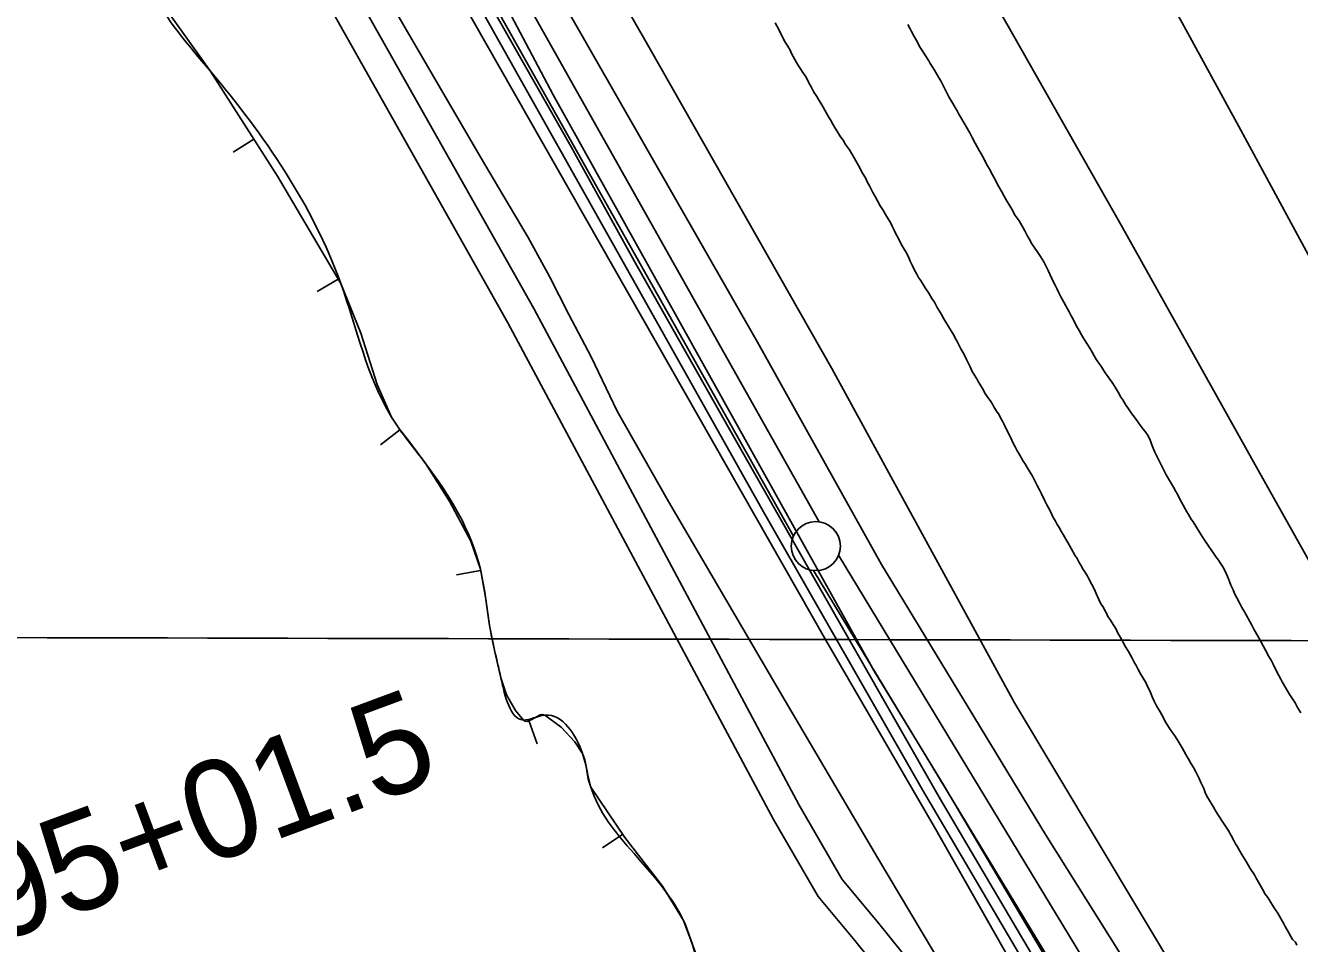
# Model space of a CAD drawing. Extents: x 3187622 to 3225504, y 800805 to 826213.
# Drawn here: x 3195483 to 3196782, y 818051 to 818987 of the extents above; entities that cross this region are included whole.
import ezdxf

# ---------------------------------------------------------------- set-up
doc = ezdxf.new("R2010")
doc.units = 0
for name, color, linetype in [('V-BORW-LINE', 7, 'Continuous'), ('V-GRID-MAJR', 7, 'Continuous'), ('V-LEVE-TOET', 7, 'Continuous'), ('V-RAIL-TRAK', 7, 'Continuous'), ('V-ROAD-CNTR', 7, 'Continuous'), ('V-SURV-IDEN', 7, 'Continuous'), ('V-SURV-LINE', 7, 'Continuous'), ('V-TOPO-SHOR', 7, 'Continuous')]:
    doc.layers.add(name, color=color, linetype=linetype)

msp = doc.modelspace()

# ---------------------------------------------------------------- linework, layer by layer
at = {"layer": 'V-BORW-LINE'}
for p, q in [((3195716.0470000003, 818871.297), (3195694.983, 818857.832)), ((3195802.022, 818728.62), (3195780.485, 818715.925)), ((3195865.014, 818574.986), (3195845.294, 818559.6190000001)), ((3195947.247, 818431.326), (3195922.6380000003, 818426.924)), ((3195996.464, 818278.415), (3196004.858, 818254.866)), ((3196092.079, 818162.635), (3196071.384, 818148.609))]:
    msp.add_line(p, q, dxfattribs=at)
msp.add_lwpolyline([(3196168.005, 818037.2540000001), (3196153.947, 818074.671), (3196132.572, 818109.742), (3196094.308, 818159.345), (3196059.6580000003, 818210.475), (3196056.811, 818218.623), (3196054.844, 818231.833), (3196053.485, 818238.468), (3196051.008, 818244.867), (3196043.409, 818256.7880000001), (3196029.214, 818271.794), (3196012.85, 818284.022), (3196010.332, 818284.737), (3196007.892, 818284.267), (3195998.694, 818279.209), (3195994.398, 818277.6780000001), (3195992.495, 818277.895), (3195990.819, 818279.045), (3195982.884, 818288.858), (3195973.7770000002, 818304.7490000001), (3195967.936, 818321.9450000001), (3195961.894, 818348.605), (3195956.4590000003, 818375.336), (3195952.1, 818404.198), (3195946.951, 818432.983), (3195937.167, 818461.523), (3195915.8000000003, 818501.626), (3195891.34, 818540.301), (3195873.619, 818563.942), (3195864.566, 818575.56), (3195856.5640000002, 818587.8420000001), (3195841.801, 818621.028), (3195825.3000000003, 818673.551), (3195804.665, 818724.137), (3195740.098, 818833.674), (3195671.573, 818940.867), (3195641.829, 818982.586), (3195612.0160000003, 819024.138)], dxfattribs=at)
msp.add_spline([(3195014.154, 820127.748), (3195051.194, 820036.459), (3195079.12, 820023.13), (3195095.7120000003, 820005.482), (3195110.87, 819937.094), (3195175.18, 819834.086), (3195197.049, 819771.025), (3195216.376, 819742.564), (3195236.043, 819732.058), (3195343.1210000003, 819557.8150000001), (3195386.444, 819443.91), (3195423.701, 819413.93), (3195435.2120000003, 819377.2540000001), (3195508.27, 819247.204), (3195522.806, 819188.056), (3195531.446, 819165.386), (3195561.3170000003, 819136.962), (3195612.0160000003, 819024.138), (3195671.573, 818940.867), (3195804.665, 818724.137), (3195856.5640000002, 818587.8420000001), (3195891.34, 818540.301), (3195946.951, 818432.983), (3195956.4590000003, 818375.336), (3195967.936, 818321.9450000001), (3195990.819, 818279.045), (3196012.85, 818284.022), (3196051.008, 818244.867), (3196059.6580000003, 818210.475), (3196153.947, 818074.671), (3196181.719, 817999.753), (3196229.435, 817932.566), (3196235.7660000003, 817878.599), (3196233.995, 817870.871), (3196216.5100000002, 817843.1780000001), (3196019.6410000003, 817732.454), (3196013.6890000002, 817705.608), (3195965.941, 817606.886), (3195937.723, 817579.993), (3195806.127, 817496.9130000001), (3195442.668, 817228.373), (3195277.136, 817095.711), (3195161.322, 817066.0260000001), (3195006.875, 816920.627), (3194988.8850000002, 816904.252), (3194750.384, 816771.517), (3194626.731, 816626.041), (3194574.393, 816615.094), (3194537.128, 816629.5380000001), (3194501.9450000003, 816686.659), (3194504.963, 816727.791), (3194556.893, 816766.49), (3194645.985, 816889.795), (3194851.122, 817135.1680000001), (3195025.557, 817293.29), (3195054.542, 817305.115), (3195088.969, 817312.308), (3195131.73, 817304.675), (3195173.611, 817273.689), (3195209.049, 817258.247), (3195260.238, 817261.312), (3195353.014, 817281.394), (3195400.754, 817303.612), (3195373.091, 817435.125), (3195339.326, 817520.9990000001), (3195289.982, 817592.801), (3195254.399, 817614.072), (3195190.759, 817615.522), (3195163.186, 817607.826), (3195157.178, 817596.796), (3195038.438, 817517.794), (3194984.543, 817508.547), (3194920.162, 817535.3300000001), (3194908.541, 817585.465), (3194818.394, 817760.0160000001), (3194797.8680000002, 817802.863), (3194765.349, 817861.172), (3194714.035, 817919.632), (3194687.018, 818000.289), (3194630.776, 818119.483), (3194667.352, 818141.816), (3194702.3910000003, 818151.491), (3194837.381, 818213.061), (3194902.293, 818255.28), (3194911.559, 818327.134), (3194902.191, 818415.296), (3194985.448, 818303.6730000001), (3195064.113, 818358.965), (3195105.49, 818400.263), (3195062.3140000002, 818499.252), (3195048.248, 818530.368), (3195002.148, 818631.921), (3194941.613, 818693.574), (3194763.916, 818992.262), (3194733.998, 819033.866), (3194637.043, 819125.688), (3194584.718, 819145.814)], degree=3, dxfattribs=at)
at = {"layer": 'V-GRID-MAJR'}
msp.add_spline([(3191823.839, 818371.837), (3197059.682, 818359.272), (3202295.526, 818347.468), (3207531.372, 818336.426), (3212767.22, 818326.145), (3218003.0700000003, 818316.626), (3223238.92, 818307.868), (3223238.921, 818307.868)], degree=3, dxfattribs=at)
at = {"layer": 'V-LEVE-TOET'}
for points in [[(3195356.313, 820325.478), (3195489.578, 820080.475), (3195647.598, 819801.257), (3195816.836, 819498.206), (3195949.288, 819261.746), (3196120.194, 818963.107), (3196305.282, 818637.483), (3196491.492, 818296.479), (3196705.215, 817939.611)], [(3197011.838, 818041.454), (3197010.273, 818077.5970000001), (3196963.6750000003, 818148.251), (3196874.1, 818294.476), (3196739.909, 818533.8520000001), (3196601.49, 818781.2490000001), (3196435.525, 819074.072), (3196262.747, 819363.899), (3196287.092, 819398.819), (3196304.068, 819412.172), (3196327.603, 819429.252), (3196345.845, 819437.9770000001), (3196363.623, 819443.762), (3196384.415, 819441.272), (3196400.917, 819427.014), (3196441.284, 819369.496), (3196462.0810000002, 819340.375), (3196495.463, 819297.937), (3196530.29, 819232.059), (3196721.974, 818880.356), (3196893.539, 818563.888), (3197078.431, 818207.479), (3197169.403, 818042.943)], [(3196419.438, 818025.357), (3196352.165, 818138.081), (3196257.5640000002, 818298.674), (3196138.622, 818501.791), (3196086.4450000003, 818593.892), (3196059.7800000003, 818649.341), (3196037.139, 818692.613), (3196017.472, 818731.273), (3195995.598, 818771.134), (3195969.779, 818814.621), (3195947.681, 818852.036), (3195925.3310000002, 818890.424), (3195842.878, 819032.321)]]:
    msp.add_lwpolyline(points, dxfattribs=at)
at = {"layer": 'V-RAIL-TRAK'}
msp.add_lwpolyline([(3194238.444, 822033.667), (3194389.349, 821767.376), (3194710.685, 821197.26), (3195003.106, 820676.953), (3195353.359, 820056.4130000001), (3195586.014, 819644.978), (3195933.752, 819028.741), (3196235.611, 818491.211), (3196397.811, 818207.715), (3196539.196, 817967.302), (3196658.29, 817767.62), (3196713.508, 817682.2000000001), (3196876.719, 817422.206), (3197092.6520000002, 817079.2440000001), (3197323.65, 816712.31)], dxfattribs=at)
at = {"layer": 'V-ROAD-CNTR'}
for points in [[(3193654.2206546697, 823085.5218015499), (3194393.590175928, 821781.8704088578), (3194932.499098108, 820818.533335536), (3195643.760675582, 819559.4038537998), (3196039.567883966, 818863.5862454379), (3196103.707755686, 818747.0574784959), (3196200.07056296, 818577.427817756), (3196283.29539651, 818430.9171107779), (3196415.948131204, 818197.967576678), (3196513.2549365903, 818033.240906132), (3196633.136696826, 817833.4593056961), (3197048.3178664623, 817166.0546405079), (3197473.064016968, 816486.1560003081), (3198091.4847801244, 815496.522979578), (3198625.8077114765, 814645.5836814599), (3198678.141606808, 814561.8538489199), (3198728.808505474, 814484.196004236), (3198769.58042393, 814407.5261575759), (3198909.843143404, 814179.8136130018), (3198994.958973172, 814024.9359227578)], [(3195343.683275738, 819857.754257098), (3195584.487794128, 819427.4791176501), (3195690.57158196, 819249.81447298), (3195813.338336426, 819032.3249079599), (3196001.352960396, 818698.5725754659), (3196271.9384192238, 818192.3325879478), (3196315.882331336, 818116.4137397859), (3196351.739259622, 818073.39182583), (3196389.489184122, 818026.485919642), (3196511.4679401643, 817945.420081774), (3196540.0998829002, 817914.703143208), (3196654.5126540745, 817773.8914248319)], [(3195317.5853279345, 819842.9562866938), (3195558.513846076, 819412.461147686), (3195664.625633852, 819234.7485031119), (3195787.20638869, 819017.5889374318), (3195975.0510130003, 818684.1386043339), (3196245.72047166, 818177.742617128), (3196291.2003807, 818099.1717742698), (3196328.5293060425, 818054.3818638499), (3196369.0232250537, 818004.0659644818), (3196491.9259792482, 817922.386127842), (3196517.45992818, 817894.993182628), (3196631.228700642, 817754.973462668)]]:
    msp.add_lwpolyline(points, dxfattribs=at)
at = {"layer": 'V-SURV-LINE'}
for points in [[(3195317.027977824, 820213.3459850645), (3196292.210038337, 818481.1388526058)], [(3196266.064727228, 818466.4275388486), (3195290.882643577, 820198.6347124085)], [(3196312.1150016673, 818447.0707953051), (3196704.3686646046, 817799.756601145)], [(3196678.7192540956, 817784.1967826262), (3196286.4651314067, 818431.5117354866)]]:
    msp.add_lwpolyline(points, dxfattribs=at)
msp.add_circle((3196288.93618, 818456.3781399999), 25, dxfattribs=at)
at = {"layer": 'V-TOPO-SHOR'}
for points in [[(3196669.743965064, 817788.9909610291), (3196420.0625454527, 818211.1327426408), (3196347.9895583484, 818329.5383643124), (3196021.0870811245, 818916.4184021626), (3195920.6997062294, 819106.8970109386), (3195681.3144276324, 819521.3166867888), (3195459.9473958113, 819917.7181158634), (3195341.5417741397, 820128.7890066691), (3194986.3249091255, 820754.2795733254), (3194837.0308644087, 821019.4052044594), (3194610.515762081, 821418.3806687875), (3194502.406281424, 821616.5813833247), (3194445.7775058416, 821716.9687582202), (3194196.09608623, 822162.2768571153), (3194075.1164293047, 822368.1996774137), (3193771.3802693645, 822908.7470806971), (3193596.3458721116, 823217.6313111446), (3193297.7577826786, 823753.0306439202), (3193179.352161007, 823964.1015347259), (3192906.5044241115, 824437.7240214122)], [(3195138.192989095, 820692.5027272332), (3195109.8786013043, 820674.484480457), (3195099.582460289, 820659.0402689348), (3195104.7305307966, 820638.4479869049), (3195475.391607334, 819989.7911029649), (3195892.385318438, 819253.6170203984), (3196229.5839366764, 818664.1629472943), (3196355.7116641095, 818437.6478449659), (3196523.0239556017, 818162.2260728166), (3196687.7622118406, 817899.6744769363), (3196744.3909874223, 817814.7313135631)], [(3195745.665308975, 819346.2822895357), (3195938.717953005, 818993.6394597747), (3196299.082888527, 818360.4267873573), (3196409.766404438, 818169.9481785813), (3196517.875885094, 817979.4695698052)], [(3196296.353, 818903.942), (3196293.899, 818907.87), (3196291.669, 818911.583), (3196289.881, 818914.86), (3196286.985, 818919.225), (3196284.079, 818924.687), (3196282.072, 818927.961), (3196278.937, 818934.302), (3196275.8170000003, 818939.1020000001), (3196273.3680000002, 818942.811), (3196271.361, 818945.867), (3196269.131, 818949.5800000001), (3196264.216, 818958.5380000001), (3196262.645, 818962.036), (3196260.412, 818965.966), (3196257.738, 818970.113), (3196254.8340000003, 818975.356), (3196251.473, 818982.3520000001), (3196249.015, 818986.721), (3196247.451, 818989.78)], [(3196382.664, 818988.13), (3196385.117, 818983.909), (3196386.608, 818981.142), (3196389.293, 818975.969), (3196392.494, 818970.0700000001), (3196394.732, 818965.774), (3196396.666, 818962.642), (3196399.637, 818957.9130000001), (3196403.948, 818951.001), (3196405.583, 818948.454), (3196407.44, 818945.4720000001), (3196409.818, 818941.761), (3196414.131, 818934.554), (3196416.29, 818930.841), (3196418.452, 818926.616), (3196419.87, 818923.849), (3196422.555, 818918.53), (3196424.5700000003, 818914.522), (3196427.619, 818909.282), (3196432.829, 818900.256), (3196434.765, 818896.834), (3196436.774, 818893.412), (3196439.977, 818887.511), (3196445.781, 818877.54), (3196448.241, 818872.878), (3196451.4420000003, 818867.052), (3196455.464, 818859.769), (3196456.953, 818857.076), (3196458.886, 818853.875), (3196460.5270000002, 818850.741), (3196462.319, 818847.098), (3196463.957, 818844.04), (3196465.522, 818841.2000000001), (3196468.95, 818834.792), (3196471.702, 818830.059), (3196473.566, 818826.417), (3196475.057, 818823.429), (3196478.481, 818817.459), (3196481.383, 818812.438), (3196483.024, 818809.378), (3196486.667, 818803.189), (3196488.603, 818799.843), (3196492.25, 818793.508), (3196496.037, 818787.907), (3196500.424, 818780.702), (3196501.986, 818777.935), (3196504.823, 818772.18), (3196506.312, 818769.485), (3196509.14, 818764.609), (3196512.3310000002, 818759.954), (3196515.372, 818755.811), (3196518.045, 818751.6630000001), (3196521.17, 818746.349), (3196523.036, 818742.634), (3196525.794, 818737.243), (3196529.5300000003, 818729.299), (3196530.949, 818726.2390000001), (3196532.886, 818722.524), (3196535.049, 818718.226), (3196536.696, 818714.509), (3196538.785, 818710.355), (3196541.836, 818704.895)], [(3196534.9020000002, 818478.427), (3196533.3310000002, 818481.925), (3196530.654, 818486.294), (3196527.969, 818491.539), (3196525.9560000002, 818495.471), (3196524.3910000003, 818498.531), (3196521.93, 818503.339), (3196518.794, 818509.6780000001), (3196516.781, 818513.829), (3196514.545, 818517.982), (3196513.199, 818520.823), (3196509.623, 818527.598), (3196506.947, 818531.964), (3196504.27, 818536.3300000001), (3196502.484, 818539.388), (3196500.254, 818543.099), (3196498.687, 818546.159), (3196495.789, 818550.742), (3196494.005, 818553.581), (3196491.992, 818557.515), (3196489.307, 818562.76), (3196487.96, 818566.041), (3196486.168, 818569.758), (3196484.6010000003, 818572.818), (3196482.588, 818576.75), (3196481.017, 818580.25), (3196479.452, 818583.088), (3196477.218, 818587.24), (3196475.653, 818590.0800000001), (3196473.202, 818594.008), (3196470.525, 818598.377), (3196468.9620000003, 818600.996), (3196467.18, 818603.615), (3196463.617, 818608.85), (3196461.612, 818611.908), (3196458.7120000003, 818616.93), (3196456.0330000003, 818621.296), (3196454.471, 818624.136), (3196452.906, 818626.9770000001), (3196450.006, 818631.78), (3196448.443, 818634.4010000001), (3196446.205, 818638.991), (3196442.619, 818646.644), (3196441.052, 818649.702), (3196438.816, 818654.072), (3196436.807, 818657.568), (3196432.557, 818665.6510000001), (3196430.994, 818668.492), (3196429.649, 818671.335), (3196426.97, 818675.92), (3196425.188, 818678.54), (3196421.397, 818684.6510000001), (3196419.3880000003, 818688.147), (3196416.933, 818692.515), (3196414.924, 818696.009), (3196412.691, 818699.7220000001), (3196409.787, 818704.965), (3196407.336, 818708.893), (3196403.989, 818714.353), (3196400.424, 818719.809), (3196397.305, 818724.609), (3196395.74, 818727.4500000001), (3196393.737, 818730.284), (3196391.73, 818733.559), (3196389.268, 818738.368), (3196387.4760000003, 818742.085), (3196385.236, 818746.894), (3196383.886, 818750.174), (3196381.205, 818755.2000000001), (3196378.971, 818759.132), (3196376.069, 818764.154), (3196373.833, 818768.527), (3196370.255, 818775.299), (3196368.688, 818778.359), (3196366.673, 818782.512), (3196364.881, 818786.2270000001), (3196361.086, 818792.779), (3196357.963, 818798.022), (3196354.6180000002, 818803.261), (3196351.716, 818808.282), (3196349.257, 818812.872), (3196347.022, 818817.0210000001), (3196343.666, 818823.579), (3196341.657, 818827.073), (3196339.416, 818831.884), (3196336.514, 818836.686), (3196332.488, 818844.554), (3196329.59, 818849.138), (3196328.023, 818852.198), (3196323.116, 818860.277), (3196321.332, 818863.113), (3196319.329, 818865.9500000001), (3196316.6550000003, 818870.316), (3196314.207, 818873.587), (3196311.0840000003, 818878.609), (3196308.6350000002, 818882.318), (3196306.4, 818886.469), (3196303.723, 818890.835), (3196301.491, 818894.5480000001), (3196299.926, 818897.608), (3196296.353, 818903.942)], [(3196541.836, 818704.895), (3196543.7, 818701.399), (3196547.202, 818695.0650000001), (3196549.287, 818691.2760000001), (3196551.222, 818687.708), (3196554.728, 818680.714), (3196557.336, 818676.1290000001), (3196559.865, 818671.761), (3196562.767, 818666.6630000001), (3196565.147, 818662.881), (3196568.1920000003, 818658.152), (3196570.648, 818653.929), (3196572.657, 818650.506), (3196575.184, 818646.359), (3196577.338, 818643.013), (3196579.27, 818640.029), (3196581.125, 818637.264), (3196583.9450000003, 818633.1190000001), (3196585.948, 818630.356), (3196587.656, 818627.811), (3196591.068, 818623.086), (3196594.113, 818618.357), (3196596.944, 818613.186), (3196599.991, 818608.238), (3196601.701, 818605.473), (3196604.4560000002, 818600.74), (3196608.8370000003, 818594.121), (3196611.061, 818591.139), (3196613.875, 818587.653), (3196617.213, 818583.074), (3196619.5870000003, 818579.73), (3196622.699, 818575.658), (3196624.698, 818573.117), (3196627.146, 818569.92), (3196629.159, 818565.912), (3196630.287, 818562.703), (3196631.268, 818559.4890000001), (3196632.6180000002, 818556.137), (3196634.412, 818552.127), (3196637.617, 818546.009), (3196639.931, 818541.346), (3196642.1720000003, 818536.609), (3196644.335, 818532.529), (3196646.196, 818529.107), (3196650.585, 818521.5380000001), (3196653.637, 818516.295), (3196655.947, 818512.072), (3196657.438, 818509.231), (3196659.899, 818504.277), (3196663.252, 818498.012), (3196665.339, 818494.228), (3196667.049, 818491.3150000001), (3196668.759, 818488.4770000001), (3196671.659, 818483.8200000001), (3196673.441, 818481.1290000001), (3196676.115, 818476.76), (3196679.9080000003, 818470.5750000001), (3196681.616, 818467.882), (3196683.326, 818465.191), (3196686.669, 818460.1), (3196689.563, 818455.9550000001), (3196691.862, 818452.608), (3196694.906, 818448.246), (3196697.058, 818445.045), (3196699.284, 818441.846), (3196700.992, 818439.2270000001), (3196703.667, 818435.079), (3196706.049, 818430.783), (3196707.468, 818427.795), (3196709.563, 818423.058), (3196710.616, 818420.139), (3196712.115, 818416.42), (3196714.21, 818411.609), (3196715.853, 818408.183), (3196718.165, 818403.667), (3196721.522, 818397.04), (3196723.234, 818393.906), (3196725.765, 818389.466), (3196727.698, 818386.337), (3196731.348, 818379.638), (3196733.287, 818375.849), (3196735.821, 818371.1140000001), (3196739.024, 818365.216), (3196742.149, 818359.756), (3196744.904, 818354.806), (3196747.218, 818350.214), (3196750.718, 818343.88), (3196753.397, 818339.294), (3196755.185, 818335.944), (3196758.619, 818328.8030000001), (3196761.003, 818324.432), (3196762.869, 818320.572), (3196764.286, 818317.876), (3196767.559, 818312.197), (3196771.4250000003, 818305.7930000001), (3196773.359, 818302.809), (3196775.364, 818299.608), (3196777.3710000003, 818296.407), (3196780.049, 818291.822), (3196783.177, 818286.286)], [(3196774.964, 818055.343), (3196772.9590000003, 818058.399), (3196771.167, 818062.1140000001), (3196767.374, 818068.446), (3196765.5840000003, 818071.942), (3196763.131, 818076.0920000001), (3196759.778, 818082.209), (3196757.552, 818085.482), (3196755.545, 818088.537), (3196751.754, 818094.6510000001), (3196749.747, 818097.925), (3196747.079, 818101.632), (3196744.396, 818106.658), (3196740.156, 818113.6460000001), (3196737.9220000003, 818117.797), (3196735.913, 818121.291), (3196731.68, 818127.6190000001), (3196729.896, 818130.677), (3196727.44, 818134.826), (3196723.201, 818142.031), (3196720.747, 818145.961), (3196718.734, 818149.676), (3196716.727, 818152.951), (3196714.9390000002, 818156.228), (3196712.259, 818161.2540000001), (3196709.131, 818166.714), (3196706.68, 818170.644), (3196703.116, 818175.88), (3196699.327, 818181.773), (3196697.097, 818185.264), (3196695.537, 818187.886), (3196693.97, 818190.946), (3196690.181, 818196.838), (3196687.502, 818201.425), (3196685.931, 818205.142), (3196684.576, 818209.083), (3196681.444, 818215.202), (3196679.648, 818219.357), (3196678.079, 818222.636), (3196676.287, 818226.351), (3196673.8340000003, 818230.501), (3196671.38, 818234.431), (3196669.8140000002, 818237.49), (3196666.242, 818243.8250000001), (3196664.008, 818247.755), (3196662.4450000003, 818250.596), (3196658.4250000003, 818257.585), (3196655.531, 818261.731), (3196653.08, 818265.439), (3196651.0810000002, 818267.838), (3196649.074, 818271.112), (3196646.843, 818274.823), (3196644.8340000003, 818278.317), (3196643.27, 818281.158), (3196639.917, 818287.275), (3196636.347, 818293.3910000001), (3196633.884, 818298.4180000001), (3196632.094, 818301.914), (3196629.394, 818308.6950000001), (3196627.1580000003, 818313.068), (3196625.5870000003, 818316.566), (3196622.683, 818321.809), (3196620.006, 818326.175), (3196617.549, 818330.5430000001), (3196615.536, 818334.478), (3196613.752, 818337.314), (3196611.511, 818342.125), (3196609.725, 818345.182), (3196607.714, 818348.895), (3196604.593, 818353.698), (3196602.357, 818358.068), (3196600.348, 818361.562), (3196596.551, 818368.335), (3196595.201, 818371.616), (3196592.75, 818375.544), (3196588.5160000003, 818381.8740000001), (3196586.732, 818384.711), (3196585.166, 818387.992), (3196583.6010000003, 818390.8300000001), (3196582.034, 818393.89), (3196579.585, 818397.601), (3196577.568, 818401.973), (3196574.428, 818408.75), (3196572.857, 818412.248), (3196570.176, 818417.274), (3196567.2660000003, 818422.9550000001), (3196565.704, 818425.796), (3196563.248, 818429.9450000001), (3196561.466, 818432.564), (3196559.011, 818436.933), (3196557.446, 818439.7710000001), (3196555.214, 818443.704), (3196552.984, 818447.1950000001), (3196549.187, 818453.968), (3196547.624, 818456.809), (3196545.836, 818460.085), (3196543.827, 818463.579), (3196540.929, 818468.1630000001), (3196539.364, 818471.003), (3196536.907, 818475.372), (3196534.9020000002, 818478.427)], [(3196779.122, 818049.308), (3196777.9930000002, 818052.517), (3196774.964, 818055.343)]]:
    msp.add_lwpolyline(points, dxfattribs=at)

# ---------------------------------------------------------------- texts
at = {"layer": 'V-SURV-IDEN'}
msp.add_text('1395+01.5', height=99.99999999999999, rotation=20.37227846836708, dxfattribs=at).set_placement((3195312.9373817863, 817998.3285313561))

doc.saveas('drawing.dxf')
